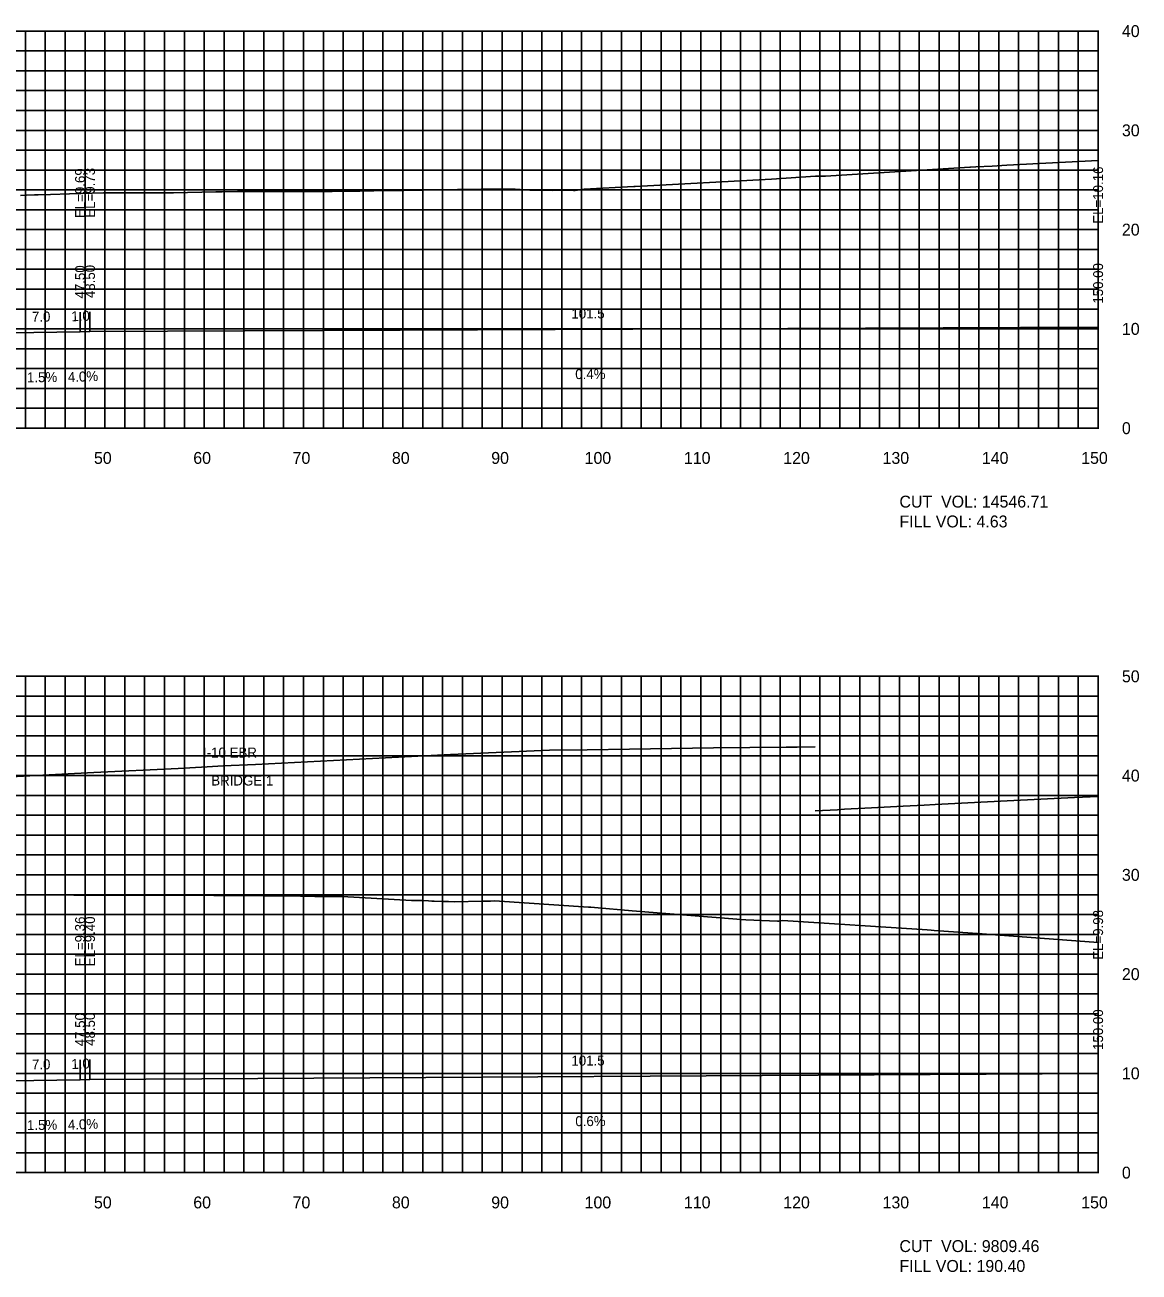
# Model space of a CAD drawing. Extents: x 1797789 to 1803805, y 249066 to 250293.
# Drawn here: x 1802673 to 1802785.1, y 250089.4 to 250215 of the extents above; entities that cross this region are included whole.
import ezdxf

# ---------------------------------------------------------------- set-up
doc = ezdxf.new("R2010")
doc.units = 0
for name, color, linetype in [('10', 7, 'Continuous'), ('3', 7, 'Continuous'), ('31', 7, 'Continuous'), ('4', 7, 'Continuous'), ('60', 7, 'Continuous'), ('ANNO-TXT', 7, 'Continuous'), ('CL-CNST', 7, 'Continuous'), ('Level 62', 7, 'Continuous'), ('M-ROADS', 7, 'Continuous')]:
    doc.layers.add(name, color=color, linetype=linetype)

msp = doc.modelspace()

# ---------------------------------------------------------------- linework, layer by layer
for p, q in [((1802678.5, 250184.12), (1802678.5, 250186.12)), ((1802679.5, 250184.16), (1802679.5, 250186.16)), ((1802781, 250184.59), (1802781, 250186.59)), ((1802678.5, 250108.79), (1802678.5, 250110.79)), ((1802679.5, 250108.83), (1802679.5, 250110.83)), ((1802781, 250109.41), (1802781, 250111.41))]:
    msp.add_line(p, q)
at = {"layer": '60'}
for p, q in [((1802781, 250174.43), (1802781, 250214.43)), ((1802781.06, 250214.43), (1802781, 250214.43)), ((1802781.06, 250204.43), (1802781, 250204.43)), ((1802781.06, 250194.43), (1802781, 250194.43)), ((1802781.06, 250184.43), (1802781, 250184.43)), ((1802481, 250174.43), (1802781, 250174.43)), ((1802681, 250174.37), (1802681, 250174.43)), ((1802691, 250174.37), (1802691, 250174.43)), ((1802701, 250174.37), (1802701, 250174.43)), ((1802711, 250174.37), (1802711, 250174.43)), ((1802721, 250174.37), (1802721, 250174.43)), ((1802731, 250174.37), (1802731, 250174.43)), ((1802741, 250174.37), (1802741, 250174.43)), ((1802751, 250174.37), (1802751, 250174.43)), ((1802761, 250174.37), (1802761, 250174.43)), ((1802771, 250174.37), (1802771, 250174.43)), ((1802781, 250174.37), (1802781, 250174.43)), ((1802781.06, 250174.43), (1802781, 250174.43)), ((1802781, 250099.43), (1802781, 250149.43)), ((1802781.06, 250149.43), (1802781, 250149.43)), ((1802781.06, 250139.43), (1802781, 250139.43)), ((1802781.06, 250129.43), (1802781, 250129.43)), ((1802781.06, 250119.43), (1802781, 250119.43)), ((1802781.06, 250109.43), (1802781, 250109.43)), ((1802481, 250099.43), (1802781, 250099.43)), ((1802681, 250099.37), (1802681, 250099.43)), ((1802691, 250099.37), (1802691, 250099.43)), ((1802701, 250099.37), (1802701, 250099.43)), ((1802711, 250099.37), (1802711, 250099.43)), ((1802721, 250099.37), (1802721, 250099.43)), ((1802731, 250099.37), (1802731, 250099.43)), ((1802741, 250099.37), (1802741, 250099.43)), ((1802751, 250099.37), (1802751, 250099.43)), ((1802761, 250099.37), (1802761, 250099.43)), ((1802771, 250099.37), (1802771, 250099.43)), ((1802781, 250099.37), (1802781, 250099.43)), ((1802781.06, 250099.43), (1802781, 250099.43))]:
    msp.add_line(p, q, dxfattribs=at)
at = {"layer": 'CL-CNST'}
for points in [[(1802481, 250187.57), (1802582.5, 250184.16), (1802583.5, 250184.12), (1802590.5, 250184.02), (1802590.5, 250184.02), (1802590.83, 250184.02), (1802591, 250183.52), (1802593, 250183.68), (1802597, 250183.77), (1802631, 250184.51), (1802665, 250183.77), (1802669, 250183.68), (1802671, 250183.52), (1802671.17, 250184.02), (1802671.5, 250184.02), (1802671.5, 250184.02), (1802678.5, 250184.12), (1802679.5, 250184.16), (1802781, 250184.59)], [(1802632.47, 250137.25), (1802644.2, 250137.87), (1802653.52, 250138.36), (1802665.04, 250138.96), (1802679.9, 250139.73), (1802688.39, 250140.16), (1802691.29, 250140.31), (1802692.92, 250140.4), (1802696.16, 250140.56), (1802706.65, 250141.08), (1802715.8, 250141.54), (1802725.76, 250141.98), (1802729.55, 250142.04), (1802733.81, 250142.1), (1802742.28, 250142.22), (1802749.58, 250142.28), (1802750.71, 250142.3), (1802752.52, 250142.31)], [(1802752.53, 250135.87), (1802754.76, 250135.99), (1802755.46, 250136.03), (1802758.17, 250136.18), (1802761.38, 250136.34), (1802763.49, 250136.46), (1802764.61, 250136.51), (1802771.84, 250136.89), (1802778.62, 250137.21), (1802781, 250137.32)], [(1802529.01, 250126.66), (1802582.5, 250108.83), (1802583.5, 250108.79), (1802590.5, 250108.69), (1802590.5, 250108.69), (1802590.83, 250108.69), (1802591, 250108.19), (1802593, 250108.35), (1802597, 250108.44), (1802631, 250109.18), (1802665, 250108.44), (1802669, 250108.35), (1802671, 250108.19), (1802671.17, 250108.69), (1802671.5, 250108.69), (1802671.5, 250108.69), (1802678.5, 250108.79), (1802679.5, 250108.83), (1802781, 250109.41)]]:
    msp.add_lwpolyline(points, dxfattribs=at)
at = {"layer": 'Level 62'}
for p, q in [((1802481, 250214.43), (1802781, 250214.43)), ((1802673, 250174.43), (1802673, 250214.43)), ((1802675, 250174.43), (1802675, 250214.43)), ((1802677, 250174.43), (1802677, 250214.43)), ((1802679, 250174.43), (1802679, 250214.43)), ((1802681, 250174.43), (1802681, 250214.43)), ((1802683, 250174.43), (1802683, 250214.43)), ((1802685, 250174.43), (1802685, 250214.43)), ((1802687, 250174.43), (1802687, 250214.43)), ((1802689, 250174.43), (1802689, 250214.43)), ((1802691, 250174.43), (1802691, 250214.43)), ((1802693, 250174.43), (1802693, 250214.43)), ((1802695, 250174.43), (1802695, 250214.43)), ((1802697, 250174.43), (1802697, 250214.43)), ((1802699, 250174.43), (1802699, 250214.43)), ((1802701, 250174.43), (1802701, 250214.43)), ((1802703, 250174.43), (1802703, 250214.43)), ((1802705, 250174.43), (1802705, 250214.43)), ((1802707, 250174.43), (1802707, 250214.43)), ((1802709, 250174.43), (1802709, 250214.43)), ((1802711, 250174.43), (1802711, 250214.43)), ((1802713, 250174.43), (1802713, 250214.43)), ((1802715, 250174.43), (1802715, 250214.43)), ((1802717, 250174.43), (1802717, 250214.43)), ((1802719, 250174.43), (1802719, 250214.43)), ((1802721, 250174.43), (1802721, 250214.43)), ((1802723, 250174.43), (1802723, 250214.43)), ((1802725, 250174.43), (1802725, 250214.43)), ((1802727, 250174.43), (1802727, 250214.43)), ((1802729, 250174.43), (1802729, 250214.43)), ((1802731, 250174.43), (1802731, 250214.43)), ((1802733, 250174.43), (1802733, 250214.43)), ((1802735, 250174.43), (1802735, 250214.43)), ((1802737, 250174.43), (1802737, 250214.43)), ((1802739, 250174.43), (1802739, 250214.43)), ((1802741, 250174.43), (1802741, 250214.43)), ((1802743, 250174.43), (1802743, 250214.43)), ((1802745, 250174.43), (1802745, 250214.43)), ((1802747, 250174.43), (1802747, 250214.43)), ((1802749, 250174.43), (1802749, 250214.43)), ((1802751, 250174.43), (1802751, 250214.43)), ((1802753, 250174.43), (1802753, 250214.43)), ((1802755, 250174.43), (1802755, 250214.43)), ((1802757, 250174.43), (1802757, 250214.43)), ((1802759, 250174.43), (1802759, 250214.43)), ((1802761, 250174.43), (1802761, 250214.43)), ((1802763, 250174.43), (1802763, 250214.43)), ((1802765, 250174.43), (1802765, 250214.43)), ((1802767, 250174.43), (1802767, 250214.43)), ((1802769, 250174.43), (1802769, 250214.43)), ((1802771, 250174.43), (1802771, 250214.43)), ((1802773, 250174.43), (1802773, 250214.43)), ((1802775, 250174.43), (1802775, 250214.43)), ((1802777, 250174.43), (1802777, 250214.43)), ((1802779, 250174.43), (1802779, 250214.43)), ((1802781, 250174.43), (1802781, 250214.43)), ((1802481, 250212.43), (1802781, 250212.43)), ((1802481, 250210.43), (1802781, 250210.43)), ((1802481, 250208.43), (1802781, 250208.43)), ((1802481, 250206.43), (1802781, 250206.43)), ((1802481, 250204.43), (1802781, 250204.43)), ((1802481, 250202.43), (1802781, 250202.43)), ((1802481, 250200.43), (1802781, 250200.43)), ((1802481, 250198.43), (1802781, 250198.43)), ((1802481, 250196.43), (1802781, 250196.43)), ((1802481, 250194.43), (1802781, 250194.43)), ((1802481, 250192.43), (1802781, 250192.43)), ((1802481, 250190.43), (1802781, 250190.43)), ((1802481, 250188.43), (1802781, 250188.43)), ((1802481, 250186.43), (1802781, 250186.43)), ((1802481, 250184.43), (1802781, 250184.43)), ((1802481, 250182.43), (1802781, 250182.43)), ((1802481, 250180.43), (1802781, 250180.43)), ((1802481, 250178.43), (1802781, 250178.43)), ((1802481, 250176.43), (1802781, 250176.43)), ((1802481, 250174.43), (1802781, 250174.43)), ((1802481, 250149.43), (1802781, 250149.43)), ((1802673, 250099.43), (1802673, 250149.43)), ((1802675, 250099.43), (1802675, 250149.43)), ((1802677, 250099.43), (1802677, 250149.43)), ((1802679, 250099.43), (1802679, 250149.43)), ((1802681, 250099.43), (1802681, 250149.43)), ((1802683, 250099.43), (1802683, 250149.43)), ((1802685, 250099.43), (1802685, 250149.43)), ((1802687, 250099.43), (1802687, 250149.43)), ((1802689, 250099.43), (1802689, 250149.43)), ((1802691, 250099.43), (1802691, 250149.43)), ((1802693, 250099.43), (1802693, 250149.43)), ((1802695, 250099.43), (1802695, 250149.43)), ((1802697, 250099.43), (1802697, 250149.43)), ((1802699, 250099.43), (1802699, 250149.43)), ((1802701, 250099.43), (1802701, 250149.43)), ((1802703, 250099.43), (1802703, 250149.43)), ((1802705, 250099.43), (1802705, 250149.43)), ((1802707, 250099.43), (1802707, 250149.43)), ((1802709, 250099.43), (1802709, 250149.43)), ((1802711, 250099.43), (1802711, 250149.43)), ((1802713, 250099.43), (1802713, 250149.43)), ((1802715, 250099.43), (1802715, 250149.43)), ((1802717, 250099.43), (1802717, 250149.43)), ((1802719, 250099.43), (1802719, 250149.43)), ((1802721, 250099.43), (1802721, 250149.43)), ((1802723, 250099.43), (1802723, 250149.43)), ((1802725, 250099.43), (1802725, 250149.43)), ((1802727, 250099.43), (1802727, 250149.43)), ((1802729, 250099.43), (1802729, 250149.43)), ((1802731, 250099.43), (1802731, 250149.43)), ((1802733, 250099.43), (1802733, 250149.43)), ((1802735, 250099.43), (1802735, 250149.43)), ((1802737, 250099.43), (1802737, 250149.43)), ((1802739, 250099.43), (1802739, 250149.43)), ((1802741, 250099.43), (1802741, 250149.43)), ((1802743, 250099.43), (1802743, 250149.43)), ((1802745, 250099.43), (1802745, 250149.43)), ((1802747, 250099.43), (1802747, 250149.43)), ((1802749, 250099.43), (1802749, 250149.43)), ((1802751, 250099.43), (1802751, 250149.43)), ((1802753, 250099.43), (1802753, 250149.43)), ((1802755, 250099.43), (1802755, 250149.43)), ((1802757, 250099.43), (1802757, 250149.43)), ((1802759, 250099.43), (1802759, 250149.43)), ((1802761, 250099.43), (1802761, 250149.43)), ((1802763, 250099.43), (1802763, 250149.43)), ((1802765, 250099.43), (1802765, 250149.43)), ((1802767, 250099.43), (1802767, 250149.43)), ((1802769, 250099.43), (1802769, 250149.43)), ((1802771, 250099.43), (1802771, 250149.43)), ((1802773, 250099.43), (1802773, 250149.43)), ((1802775, 250099.43), (1802775, 250149.43)), ((1802777, 250099.43), (1802777, 250149.43)), ((1802779, 250099.43), (1802779, 250149.43)), ((1802781, 250099.43), (1802781, 250149.43)), ((1802481, 250147.43), (1802781, 250147.43)), ((1802481, 250145.43), (1802781, 250145.43)), ((1802481, 250143.43), (1802781, 250143.43)), ((1802481, 250141.43), (1802781, 250141.43)), ((1802481, 250139.43), (1802781, 250139.43)), ((1802481, 250137.43), (1802781, 250137.43)), ((1802481, 250135.43), (1802781, 250135.43)), ((1802481, 250133.43), (1802781, 250133.43)), ((1802481, 250131.43), (1802781, 250131.43)), ((1802481, 250129.43), (1802781, 250129.43)), ((1802481, 250127.43), (1802781, 250127.43)), ((1802481, 250125.43), (1802781, 250125.43)), ((1802481, 250123.43), (1802781, 250123.43)), ((1802481, 250121.43), (1802781, 250121.43)), ((1802481, 250119.43), (1802781, 250119.43)), ((1802481, 250117.43), (1802781, 250117.43)), ((1802481, 250115.43), (1802781, 250115.43)), ((1802481, 250113.43), (1802781, 250113.43)), ((1802481, 250111.43), (1802781, 250111.43)), ((1802481, 250109.43), (1802781, 250109.43)), ((1802481, 250107.43), (1802781, 250107.43)), ((1802481, 250105.43), (1802781, 250105.43)), ((1802481, 250103.43), (1802781, 250103.43)), ((1802481, 250101.43), (1802781, 250101.43)), ((1802481, 250099.43), (1802781, 250099.43))]:
    msp.add_line(p, q, dxfattribs=at)
at = {"layer": 'M-ROADS'}
for points in [[(1802672.5, 250197.87), (1802673.1, 250197.89), (1802673.92, 250197.92), (1802674.27, 250197.93), (1802675.51, 250197.97), (1802677.44, 250198.02), (1802680.85, 250198.12), (1802680.91, 250198.12), (1802681.33, 250198.14), (1802681.33, 250198.14), (1802681.55, 250198.14), (1802683.43, 250198.15), (1802683.52, 250198.15), (1802685.08, 250198.15), (1802686.18, 250198.15), (1802686.32, 250198.15), (1802687.22, 250198.15), (1802687.91, 250198.15), (1802692.18, 250198.24), (1802692.81, 250198.24), (1802694.36, 250198.26), (1802695.12, 250198.27), (1802696.55, 250198.28), (1802703.43, 250198.28), (1802703.89, 250198.28), (1802704.43, 250198.29), (1802705.05, 250198.3), (1802705.78, 250198.31), (1802706.66, 250198.32), (1802706.99, 250198.33), (1802708.08, 250198.34), (1802709.42, 250198.36), (1802711.11, 250198.38), (1802716.51, 250198.46), (1802717.58, 250198.47), (1802718.9, 250198.49), (1802718.95, 250198.49), (1802720.54, 250198.51), (1802720.75, 250198.51), (1802720.91, 250198.51), (1802721.03, 250198.51), (1802721.13, 250198.5), (1802721.21, 250198.5), (1802721.28, 250198.5), (1802721.34, 250198.5), (1802721.39, 250198.5), (1802721.43, 250198.5), (1802721.47, 250198.5), (1802721.5, 250198.5), (1802722.31, 250198.5), (1802723.79, 250198.39), (1802726.07, 250198.38), (1802726.71, 250198.39), (1802728.19, 250198.36), (1802728.36, 250198.36), (1802729.27, 250198.5), (1802734.24, 250198.79), (1802734.39, 250198.79), (1802748.11, 250199.51), (1802752.55, 250199.83), (1802752.58, 250199.83), (1802752.93, 250199.83), (1802753.18, 250199.83), (1802753.51, 250199.83), (1802753.53, 250199.83), (1802753.54, 250199.83), (1802768.08, 250200.71), (1802768.17, 250200.71), (1802768.69, 250200.75), (1802770.33, 250200.83), (1802771.8, 250200.92), (1802781, 250201.38)], [(1802672.37, 250127.41), (1802673.09, 250127.41), (1802673.73, 250127.41), (1802674.55, 250127.41), (1802675.9, 250127.4), (1802676.73, 250127.4), (1802677.88, 250127.39), (1802678.86, 250127.39), (1802678.9, 250127.39), (1802679.96, 250127.39), (1802681.08, 250127.39), (1802681.99, 250127.38), (1802683.26, 250127.38), (1802683.62, 250127.38), (1802685.07, 250127.38), (1802685.44, 250127.38), (1802686.04, 250127.38), (1802687.62, 250127.37), (1802688.06, 250127.37), (1802689.78, 250127.37), (1802689.79, 250127.37), (1802690.1, 250127.37), (1802691.97, 250127.36), (1802692.13, 250127.36), (1802694.15, 250127.36), (1802694.16, 250127.36), (1802694.37, 250127.36), (1802696.97, 250127.33), (1802699.09, 250127.3), (1802700.69, 250127.28), (1802700.89, 250127.28), (1802702.14, 250127.26), (1802703.14, 250127.25), (1802703.95, 250127.24), (1802704.17, 250127.25), (1802704.9, 250127.24), (1802711.88, 250126.86), (1802712.92, 250126.83), (1802713.58, 250126.81), (1802713.93, 250126.79), (1802714.16, 250126.78), (1802714.92, 250126.76), (1802715.59, 250126.74), (1802716.19, 250126.72), (1802719, 250126.78), (1802719.82, 250126.79), (1802720.22, 250126.82), (1802729.68, 250126.19), (1802729.92, 250126.16), (1802730.3, 250126.13), (1802734.08, 250125.81), (1802745.08, 250124.94), (1802745.53, 250124.89), (1802748.72, 250124.76), (1802748.86, 250124.78), (1802749.27, 250124.83), (1802763.78, 250123.9), (1802764.21, 250123.86), (1802764.5, 250123.83), (1802769.33, 250123.48), (1802781, 250122.63)]]:
    msp.add_lwpolyline(points, dxfattribs=at)

# ---------------------------------------------------------------- texts
at = {"layer": '10'}
for s, p in [('50', (1802679.9, 250170.83)), ('60', (1802689.9, 250170.83)), ('70', (1802699.9, 250170.83)), ('80', (1802709.9, 250170.83)), ('90', (1802719.9, 250170.83)), ('100', (1802729.3, 250170.83)), ('110', (1802739.3, 250170.83)), ('120', (1802749.3, 250170.83)), ('130', (1802759.3, 250170.83)), ('140', (1802769.3, 250170.83)), ('150', (1802779.3, 250170.83)), ('50', (1802679.9, 250095.83)), ('60', (1802689.9, 250095.83)), ('70', (1802699.9, 250095.83)), ('80', (1802709.9, 250095.83)), ('90', (1802719.9, 250095.83)), ('100', (1802729.3, 250095.83)), ('110', (1802739.3, 250095.83)), ('120', (1802749.3, 250095.83)), ('130', (1802759.3, 250095.83)), ('140', (1802769.3, 250095.83)), ('150', (1802779.3, 250095.83))]:
    msp.add_text(s, height=1.2, dxfattribs=at).set_placement(p)
at = {"layer": '3'}
for s, p in [('EL=10.16', (1802781.5, 250195.02)), ('EL=9.69', (1802679, 250195.59)), ('EL=9.73', (1802680, 250195.63)), ('47.50', (1802679, 250187.49)), ('48.50', (1802680, 250187.53)), ('150.00', (1802781.5, 250186.97)), ('EL=9.98', (1802781.5, 250120.87)), ('EL=9.36', (1802679, 250120.21)), ('EL=9.40', (1802680, 250120.22)), ('47.50', (1802679, 250112.16)), ('48.50', (1802680, 250112.2)), ('150.00', (1802781.5, 250111.79))]:
    msp.add_text(s, height=1, rotation=90, dxfattribs=at).set_placement(p)
for s, p in [('I-10 EBR ', (1802690.88, 250141.25)), ('BRIDGE 1', (1802691.71, 250138.43))]:
    msp.add_text(s, height=1, dxfattribs=at).set_placement(p)
at = {"layer": '31'}
for s, p in [('40', (1802783.4, 250213.83)), ('30', (1802783.4, 250203.83)), ('20', (1802783.4, 250193.83)), ('10', (1802783.4, 250183.83)), ('0', (1802783.4, 250173.83)), ('50', (1802783.4, 250148.83)), ('40', (1802783.4, 250138.83)), ('30', (1802783.4, 250128.83)), ('20', (1802783.4, 250118.83)), ('10', (1802783.4, 250108.83)), ('0', (1802783.4, 250098.83))]:
    msp.add_text(s, height=1.2, dxfattribs=at).set_placement(p)
at = {"layer": '4'}
for s, rotation, p in [('7.0', 0.8594, (1802673.66, 250185.15)), ('1.0', 2.2906, (1802677.64, 250185.19)), ('101.5', 0.243, (1802727.97, 250185.47)), ('1.5%', 0.8594, (1802673.16, 250179.04)), ('4.0%', 2.2906, (1802677.29, 250179.07)), ('0.4%', 0.243, (1802728.36, 250179.37)), ('7.0', 0.8594, (1802673.66, 250109.82)), ('1.0', 2.2906, (1802677.64, 250109.86)), ('101.5', 0.3251, (1802727.97, 250110.21)), ('1.5%', 0.8594, (1802673.16, 250103.71)), ('4.0%', 2.2906, (1802677.29, 250103.74)), ('0.6%', 0.3251, (1802728.37, 250104.11))]:
    msp.add_text(s, height=1, rotation=rotation, dxfattribs=at).set_placement(p)
at = {"layer": 'ANNO-TXT'}
for s, p in [('CUT  VOL: 14546.71', (1802761, 250166.43)), ('FILL VOL: 4.63', (1802761, 250164.43)), ('CUT  VOL: 9809.46', (1802761, 250091.43)), ('FILL VOL: 190.40', (1802761, 250089.43))]:
    msp.add_text(s, height=1.2, dxfattribs=at).set_placement(p)

doc.saveas('drawing.dxf')
